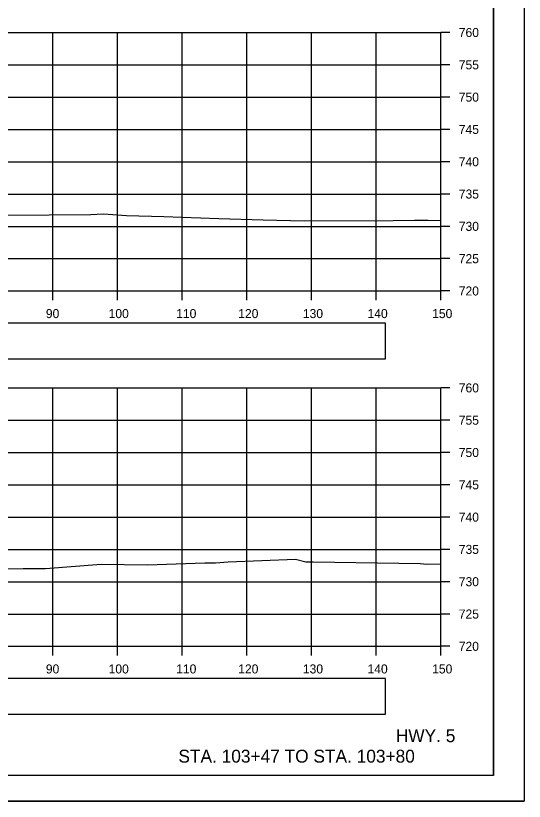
# Model space of a CAD drawing. Extents: x 1202951 to 1376887, y 378065 to 728038.
# Drawn here: x 1376668.9 to 1376747.6, y 379047.8 to 379169.4 of the extents above; entities that cross this region are included whole.
import ezdxf

# ---------------------------------------------------------------- set-up
doc = ezdxf.new("R2010")
doc.units = 0
for name, color, linetype in [('R_Alt Surface', 7, 'Continuous'), ('R_Axis', 7, 'Continuous'), ('R_Axis Annot', 7, 'Continuous'), ('R_Border', 7, 'Continuous'), ('R_Draft', 7, 'Continuous'), ('R_Exist Surface', 7, 'Continuous'), ('R_Grid', 7, 'Continuous'), ('R_No Plot', 7, 'Continuous')]:
    doc.layers.add(name, color=color, linetype=linetype)

msp = doc.modelspace()

# ---------------------------------------------------------------- linework, layer by layer
at = {"layer": 'R_Alt Surface'}
for points in [[(1376615.43, 379116.31), (1376726.14, 379116.31), (1376726.14, 379121.83), (1376615.43, 379121.83)], [(1376615.43, 379061.31), (1376726.14, 379061.31), (1376726.14, 379066.83), (1376615.43, 379066.83)]]:
    msp.add_lwpolyline(points, close=True, dxfattribs=at)
at = {"layer": 'R_Axis'}
for p, q in [((1376734.67, 379126.83), (1376734.67, 379166.83)), ((1376736.07, 379166.83), (1376734.67, 379166.83)), ((1376736.07, 379161.83), (1376734.67, 379161.83)), ((1376736.07, 379156.83), (1376734.67, 379156.83)), ((1376736.07, 379151.83), (1376734.67, 379151.83)), ((1376736.07, 379146.83), (1376734.67, 379146.83)), ((1376736.07, 379141.83), (1376734.67, 379141.83)), ((1376736.07, 379136.83), (1376734.67, 379136.83)), ((1376736.07, 379131.83), (1376734.67, 379131.83)), ((1376434.67, 379126.83), (1376734.67, 379126.83)), ((1376674.67, 379125.43), (1376674.67, 379126.83)), ((1376684.67, 379125.43), (1376684.67, 379126.83)), ((1376694.67, 379125.43), (1376694.67, 379126.83)), ((1376704.67, 379125.43), (1376704.67, 379126.83)), ((1376714.67, 379125.43), (1376714.67, 379126.83)), ((1376724.67, 379125.43), (1376724.67, 379126.83)), ((1376734.67, 379125.43), (1376734.67, 379126.83)), ((1376736.07, 379126.83), (1376734.67, 379126.83)), ((1376734.67, 379071.83), (1376734.67, 379111.83)), ((1376736.07, 379111.83), (1376734.67, 379111.83)), ((1376736.07, 379106.83), (1376734.67, 379106.83)), ((1376736.07, 379101.83), (1376734.67, 379101.83)), ((1376736.07, 379096.83), (1376734.67, 379096.83)), ((1376736.07, 379091.83), (1376734.67, 379091.83)), ((1376736.07, 379086.83), (1376734.67, 379086.83)), ((1376736.07, 379081.83), (1376734.67, 379081.83)), ((1376736.07, 379076.83), (1376734.67, 379076.83)), ((1376434.67, 379071.83), (1376734.67, 379071.83)), ((1376674.67, 379070.43), (1376674.67, 379071.83)), ((1376684.67, 379070.43), (1376684.67, 379071.83)), ((1376694.67, 379070.43), (1376694.67, 379071.83)), ((1376704.67, 379070.43), (1376704.67, 379071.83)), ((1376714.67, 379070.43), (1376714.67, 379071.83)), ((1376724.67, 379070.43), (1376724.67, 379071.83)), ((1376734.67, 379070.43), (1376734.67, 379071.83)), ((1376736.07, 379071.83), (1376734.67, 379071.83))]:
    msp.add_line(p, q, dxfattribs=at)
at = {"layer": 'R_Border'}
for q in [(1376742.85, 379257.29), (1376426.67, 379051.83)]:
    msp.add_line((1376742.85, 379051.83), q, dxfattribs=at)
at = {"layer": 'R_Exist Surface'}
for points in [[(1376667.68, 379138.56), (1376680.53, 379138.64), (1376682.5, 379138.76), (1376686.06, 379138.51), (1376691.83, 379138.34), (1376700.34, 379138.02), (1376707.22, 379137.82), (1376713.53, 379137.68), (1376727.32, 379137.76), (1376730.61, 379137.8), (1376731.9, 379137.81), (1376732.72, 379137.79), (1376734.67, 379137.74)], [(1376667.35, 379083.84), (1376670.1, 379083.86), (1376673.56, 379083.88), (1376682.13, 379084.54), (1376689.31, 379084.42), (1376698.21, 379084.76), (1376699.85, 379084.75), (1376701.77, 379084.89), (1376712.23, 379085.33), (1376713.83, 379084.92), (1376714.09, 379084.91), (1376714.95, 379084.89), (1376731.49, 379084.66), (1376732.53, 379084.57), (1376734.67, 379084.61)]]:
    msp.add_lwpolyline(points, dxfattribs=at)
at = {"layer": 'R_Grid'}
for p, q in [((1376434.67, 379166.83), (1376734.67, 379166.83)), ((1376674.67, 379126.83), (1376674.67, 379166.83)), ((1376684.67, 379126.83), (1376684.67, 379166.83)), ((1376694.67, 379126.83), (1376694.67, 379166.83)), ((1376704.67, 379126.83), (1376704.67, 379166.83)), ((1376714.67, 379126.83), (1376714.67, 379166.83)), ((1376724.67, 379126.83), (1376724.67, 379166.83)), ((1376734.67, 379126.83), (1376734.67, 379166.83)), ((1376434.67, 379161.83), (1376734.67, 379161.83)), ((1376434.67, 379156.83), (1376734.67, 379156.83)), ((1376434.67, 379151.83), (1376734.67, 379151.83)), ((1376434.67, 379146.83), (1376734.67, 379146.83)), ((1376434.67, 379141.83), (1376734.67, 379141.83)), ((1376434.67, 379136.83), (1376734.67, 379136.83)), ((1376434.67, 379131.83), (1376734.67, 379131.83)), ((1376434.67, 379126.83), (1376734.67, 379126.83)), ((1376434.67, 379111.83), (1376734.67, 379111.83)), ((1376674.67, 379071.83), (1376674.67, 379111.83)), ((1376684.67, 379071.83), (1376684.67, 379111.83)), ((1376694.67, 379071.83), (1376694.67, 379111.83)), ((1376704.67, 379071.83), (1376704.67, 379111.83)), ((1376714.67, 379071.83), (1376714.67, 379111.83)), ((1376724.67, 379071.83), (1376724.67, 379111.83)), ((1376734.67, 379071.83), (1376734.67, 379111.83)), ((1376434.67, 379106.83), (1376734.67, 379106.83)), ((1376434.67, 379101.83), (1376734.67, 379101.83)), ((1376434.67, 379096.83), (1376734.67, 379096.83)), ((1376434.67, 379091.83), (1376734.67, 379091.83)), ((1376434.67, 379086.83), (1376734.67, 379086.83)), ((1376434.67, 379081.83), (1376734.67, 379081.83)), ((1376434.67, 379076.83), (1376734.67, 379076.83)), ((1376434.67, 379071.83), (1376734.67, 379071.83))]:
    msp.add_line(p, q, dxfattribs=at)
at = {"layer": 'R_No Plot'}
msp.add_line((1376414.27, 379047.85), (1376747.6, 379047.85), dxfattribs=at)
for points in [[(1376414.26, 379261.19), (1376747.6, 379261.19), (1376747.6, 379047.85), (1376414.26, 379047.85)], [(1376660.59, 379257.29), (1376680.21, 379257.29), (1376680.21, 379247.41), (1376696.32, 379247.41), (1376719.52, 379247.41), (1376719.64, 379219.25), (1376742.85, 379219.25), (1376742.85, 379051.83), (1376426.67, 379051.83), (1376426.67, 379257.29)]]:
    msp.add_lwpolyline(points, close=True, dxfattribs=at)

# ---------------------------------------------------------------- texts
at = {"layer": 'R_Axis Annot'}
for s, p in [('760', (1376737.47, 379166.13)), ('755', (1376737.47, 379161.13)), ('750', (1376737.47, 379156.13)), ('745', (1376737.47, 379151.13)), ('740', (1376737.47, 379146.13)), ('735', (1376737.47, 379141.13)), ('730', (1376737.47, 379136.13)), ('725', (1376737.47, 379131.13)), ('720', (1376737.47, 379126.13)), ('90', (1376673.59, 379122.63)), ('100', (1376683.3, 379122.63)), ('110', (1376693.75, 379122.63)), ('120', (1376703.35, 379122.63)), ('130', (1376713.35, 379122.63)), ('140', (1376723.35, 379122.63)), ('150', (1376733.35, 379122.63)), ('760', (1376737.47, 379111.13)), ('755', (1376737.47, 379106.13)), ('750', (1376737.47, 379101.13)), ('745', (1376737.47, 379096.13)), ('740', (1376737.47, 379091.13)), ('735', (1376737.47, 379086.13)), ('730', (1376737.47, 379081.13)), ('725', (1376737.47, 379076.13)), ('720', (1376737.47, 379071.13)), ('90', (1376673.59, 379067.63)), ('100', (1376683.3, 379067.63)), ('110', (1376693.75, 379067.63)), ('120', (1376703.35, 379067.63)), ('130', (1376713.35, 379067.63)), ('140', (1376723.35, 379067.63)), ('150', (1376733.35, 379067.63))]:
    msp.add_text(s, height=1.4, dxfattribs=at).set_placement(p)
at = {"layer": 'R_Draft'}
for s, p in [('HWY. 5', (1376727.73, 379057)), ('STA. 103+47 TO STA. 103+80', (1376694.1, 379053.83))]:
    msp.add_text(s, height=2, dxfattribs=at).set_placement(p)

doc.saveas('drawing.dxf')
